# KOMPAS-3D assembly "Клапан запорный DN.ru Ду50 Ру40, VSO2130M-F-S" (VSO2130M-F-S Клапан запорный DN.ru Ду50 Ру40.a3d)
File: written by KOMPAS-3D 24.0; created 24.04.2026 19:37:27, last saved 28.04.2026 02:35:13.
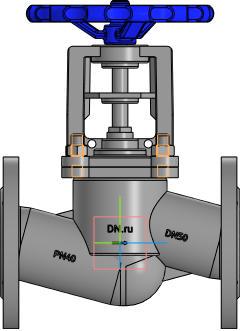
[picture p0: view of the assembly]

Document properties: Автор: DN.ru; Полное имя файла: C:\Работа\ГОТОВЫЕ ИСХОДНИКИ\VSO2130M-F-S Клапан запорный сильфонный DN.ru Ду15-100 Ру40\исходные материалы\DN50\VSO2130M-F-S Клапан запорный DN.ru Ду50 Ру40.a3d

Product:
- Component [detail]: Корпус  | qty 1  | pos. 1  | Масса: 6.9; Автор: R2D2; source file: Korpus.m3d
- Component [detail]: Деталь  | qty 1  | pos. 2  | Масса: 2.809972; Автор: mrdid; source file: rama.m3d
- Component [detail]: Деталь2  | qty 1  | pos. 3  | Масса: 1.255283; Автор: R2D2; additional columns: Типовые; source file: shturval.m3d
- Component [standard]: Шпилька М12-6gx30 ГОСТ 22032-76  | qty 4  | Масса: 0.03184; Раздел спецификации: Стандартные изделия; Рассекать на разрезах: no
- Component [standard]: Гайка М12-6H ГОСТ 5915-70  | qty 4  | Масса: 0.0184; Раздел спецификации: Стандартные изделия; Рассекать на разрезах: no
- Part/product: Клапан запорный DN.ru Ду50 Ру40  | designation VSO2130M-F-S
    Масса: 12
    Раздел спецификации: Прочие изделия
    Примечание: D090-01975

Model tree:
1. Контекстная связь:1  (with: Контекстная связь (Деталь):1)
2. Контекстная связь:2  (with: Контекстная связь (Корпус):2)
3. Массив по концентрической сетке:1  (4 pattern instances)
     Шаг 2 = 360
4. Контекстная связь:3  (with: Эскиз:2, Ребро.Элемент выдавливания:14, Контекстная связь (Деталь):3, Грань.Элемент выдавливания:1, Грань.Элемент выдавливания:15, Грань.Элемент выдавливания:3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)  (labels: Грань.Твердое тело1)
     Угол = 8

Referenced files in C:\Работа\ГОТОВЫЕ ИСХОДНИКИ\VSO2130M-F-S Клапан запорный сильфонный DN.ru Ду15-100 Ру40\исходные материалы\DN50\: Korpus.m3d, rama.m3d, shturval.m3d
Referenced files in C:\Program Files\ASCON\KOMPAS-3D v24\Libs\PolynomLib\DATA\vault\Methods\Kompas\3D\: PLib_Stud_1_900.m3d, PLib_Nut_OST92_900.m3d
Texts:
  Крепежное изделие ГОСТ
  BOSimple***PART:68500c15-de1b-e238-4ced-fd9f0c14e563***SHORTLOC:Root±30±20±10±120±10±20[Нет;Без покрытия;Без указания материала;-;12;30;1,75;1,75]
  BOSimple***PART:dfaf85ed-3e43-003f-b29c-9c5b054070d3***SHORTLOC:Root±30±10±20±©{}110±10±50±60[Нет;Без покрытия;Без указания материала;-;12;1,75;19]
  Программные изделия  и базы данных
  VSO2130M-F-S
  Деталь2 Деталь2
  Шпилька М12-6gx30 ГОСТ 22032-76 (1)
  cut1
  Гайка М12-6H ГОСТ 5915-70 (1)
  bcut1
  hole1
  hcut1
  hole2
  Плоскость XY.Начало координат
  Plane. Начало координат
